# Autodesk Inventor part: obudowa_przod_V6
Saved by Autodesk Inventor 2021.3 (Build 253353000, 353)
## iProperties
Created: 2023-01
Part Number: obudowa_przod_V6
Material: Generic
Document SubType Name: Modeling
Designer: AdminForWorker
Density: 1 g/cm^3
Appearance: Default
Title: obudowa_przod_V6
Author: AdminForWorker
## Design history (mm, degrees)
feature "MainBody"
feature "T2"
feature "T_GORA"
feature "S"
body "Solid1"
body "Solid2"
body "Solid3"
body "Solid4"
